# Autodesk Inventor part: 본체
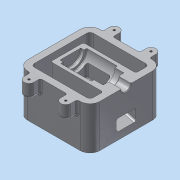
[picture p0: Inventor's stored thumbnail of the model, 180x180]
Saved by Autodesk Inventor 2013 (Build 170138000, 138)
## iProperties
Created: 2018-01
Part Number: 본체
Material: 알루미늄 6061
Document SubType Name: Modeling
Designer: dgall
Density: 2.71 g/cm^3
Mass: 998.337 g
Surface Area: 834.618 cm^2
Volume: 368.39 cm^3
Author: dgall
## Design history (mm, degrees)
sketch "스케치1"
  geometry: L1 (-55, 55)-(55, 55); L2 (55, 55)-(55, -55); L3 (55, -55)-(-55, -55); L4 (-55, -55)-(-55, 55); L5 (45, 45)-(-45, 45); L6 (-45, 45)-(-45, -45); L7 (-45, -45)-(45, -45); L8 (45, -45)-(45, 45); 3 further points
  constraints: 16 end point, 4 parallel, 2 midpoint, 2 perpendicular, 1 horizontal, 1 horizontal alignment, 1 vertical alignment, 3 other
  dimensions: "d0" = 110 distance of L1.start L1.end; "d2" = 110 distance of L1.end L2.end; "d3" = 10 distance between parallel lines of L5 L1
extrude "돌출1" new body sketch "스케치1" distance "d4" = 65; taper "d5" = 0 deg
sketch "스케치2"
  geometry: L1 (55, 55)-(-55, 55) reference; L2 (-55, 55)-(-55, -55) reference; L3 (-35.5, 65)-(-35.5, 55); L4 (-20.5, 65)-(-20.5, 55); L5 (20.5, 65)-(20.5, 55); L6 (35.5, 65)-(35.5, 55); A1 r 7.5 centre (-28, 65) between (-20.5, 65) and (-35.5, 65); A2 r 7.5 centre (28, 65) between (35.5, 65) and (20.5, 65); 1 further point
  constraints: 8 end point, 4 perpendicular, 4 point on circle, 4 point on line, 4 tangent, 2 centre point, 1 equal radius
  dimensions: "d6" = 7.5 radius of A1; "d7" = 10 distance from line of L1 A1.centre; "d8" = 27 distance from line of L2 A1.centre; "d9" = 10 distance from line of L1 A2.centre; "d10" = 56 distance of A2.centre A1.centre
extrude "돌출2" join sketch "스케치2" distance "d11" = 20; taper "d12" = 0 deg
sketch "스케치3"
  geometry: A1 r 7.5 centre (28, 65) between (35.5, 65) and (20.5, 65) reference; A2 r 7.5 centre (-28, 65) between (-20.5, 65) and (-35.5, 65) reference; 3 further points
  constraints: 2 coincident
hole "구멍1" sketch "스케치3" at (-28, 65), (28, 65) diameter "d13" = 3.242; stored, may be unused: countersink angle "d17" = 90 deg, drill point angle "d19" = 118 deg; dims "d14" = 9, "d15" = 4, "d16" = 2, "d18" = 11
fillet "모깎기1" dims "d20" = 15
fillet "모깎기2" dims "d21" = 5
fillet "모깎기3" dims "d22" = 3
sketch "스케치4"
  geometry: L1 (-45, 65)-(-45, 0) reference; L2 (-45, 0)-(-55, 0) reference; L3 (-55, 0)-(-55, 65) reference; L4 (-55, 65)-(-45, 65) reference; L5 (55, 65)-(55, 0) reference; L6 (55, 0)-(45, 0) reference; L7 (45, 0)-(45, 65) reference; L8 (45, 65)-(55, 65) reference; L9 (-45, 8.564)-(35, 30); L10 (40, 0)-(-40, 0) reference; L11 (35, 30)-(35, 65); L12 (35, 65)-(-45, 65); 1 further point
  constraints: 6 end point, 2 perpendicular, 1 point on line
  dimensions: "d23" = 105 deg angle of L9 L1; "d24" = 30 distance from line of L10 L9.end; "d25" = 20 distance between parallel lines of L5 L11
extrude "돌출3" join sketch "스케치4" stored distance "d26" = 50; taper "d27" = 0 deg
sketch "스케치5"
  geometry: L1 (-65, 0)-(-65, 80) reference; C1 r 7.5 at (-65, 40); 1 further point
  constraints: 1 centre point, 1 midpoint
  dimensions: "d28" = 7.5 radius of C1
extrude "돌출4" cut sketch "스케치5" distance "d30" = 85; taper "d31" = 0 deg
sketch "스케치6"
  geometry: C1 r 16 at (-65, 40); A1 r 7.5 centre (-65, 40) between (-65, 32.5) and (-65, 47.5) reference; 1 further point
  constraints: 1 centre point, 1 coincident
  dimensions: "d32" = 16 radius of C1
extrude "돌출5" cut sketch "스케치6" distance "d34" = 66; taper "d35" = 0 deg
node "작업 평면1"
sketch "스케치7"
  geometry: L1 (-27.321, 15)-(-65, 15) reference; L2 (-65, 15)-(-65, 24) reference; L3 (-65, 56)-(-65, 65) reference; L4 (-65, 65)-(-27.321, 65) reference; L5 (-27.321, 65)-(-27.321, 15) reference; L6 (-65, -5)-(0, -5) reference; L7 (0, -5)-(0, -15) reference; L8 (0, -15)-(-42, -15) reference; L9 (-45, -18)-(-45, -28.354) reference; L10 (-48, -31.874)-(-65, -31.874) reference; L11 (-65, -31.874)-(-65, -5) reference; L12 (0, 85)-(-65, 85) reference; L13 (-65, 85)-(-65, 111.874) reference; L14 (-65, 111.874)-(-48, 111.874) reference; L15 (-45, 108.354)-(-45, 98) reference; L16 (-42, 95)-(0, 95) reference; L17 (0, 95)-(0, 85) reference; C1 r 20 at (-65, 40); A1 r 16 centre (-65, 40) between (-65, 24) and (-65, 56) reference; A2 r 3 centre (-42, -18) between (-42, -15) and (-45, -18) reference; A3 r 3 centre (-42, 98) between (-45, 98) and (-42, 95) reference; 1 further point
  constraints: 1 centre point, 1 coincident, 2 other
  dimensions: "d37" = 20 radius of C1
extrude "돌출6" cut sketch "스케치7" distance "d39" = 47; taper "d40" = 0 deg
sketch "스케치8"
  geometry: L1 (35, 65)-(35, 30) reference; L2 (35, 30)-(-45, 8.564) reference; L3 (-45, 8.564)-(-45, 0) reference; L4 (-45, 0)-(-55, 0) reference; L5 (-55, 0)-(-55, 57.5) reference; L6 (-55, 57.5)-(-36, 57.5) reference; L7 (-36, 57.5)-(-36, 49) reference; L8 (-36, 49)-(-22, 49) reference; L9 (-22, 49)-(-22, 45) reference; L10 (-22, 45)-(25, 45) reference; L11 (25, 45)-(25, 49) reference; L12 (25, 49)-(30, 49) reference; L13 (30, 49)-(30, 65) reference; L14 (30, 65)-(35, 65) reference; L15 (55, 65)-(55, 0) reference; L16 (55, 0)-(45, 0) reference; L17 (45, 0)-(45, 65) reference; L18 (45, 65)-(55, 65) reference; L19 (-17, 39.243)-(-55, 29.061); L20 (20, 31.157)-(-55, 11.061); L21 (-17, 39.243)-(-17, 55); L22 (-17, 55)-(20, 55); L23 (20, 55)-(20, 31.157); 1 further point
  constraints: 10 end point, 3 parallel, 2 perpendicular, 2 point on line
  dimensions: "d41" = 5 distance between parallel lines of L2 L20; "d43" = 18 distance of L20.end L19.end; "d45" = 5 distance between parallel lines of L9 L21; "d46" = 37 distance of L21.end L22.end; "d47" = 10 distance between parallel lines of L10 L22
extrude "돌출7" cut sketch "스케치8" stored distance "d48" = 30; taper "d49" = 0 deg
fillet "모깎기4" dims "d50" = 3
fillet "모깎기5" dims "d51" = 3
fillet "모깎기6" dims "d52" = 1
chamfer "모따기1" distance "d53" = 1; stored, may be unused: second distance "d54" = 2, angle "d55" = 45 deg
sketch "스케치9" dims "d11" = 20
  geometry: L1 (0, 0)-(80, 0) reference; L2 (95, -65)-(95, 0) reference; 2 further points
  constraints: 1 other
  dimensions: "d56" = 20 distance from line of L1 point (40, -20); "d57" = 55 distance from line of L2 point (40, -20)
feature "엠보싱1" sketch "스케치9" dims "d0" = 110, "d2" = 110, "d3" = 10, "d58" = 0.5, "d59" = 0
fillet "모깎기7" dims "d60" = 3
fillet "모깎기8" dims "d61" = 3
node "솔리드1"
mirror "대칭1"
node "절단 모서리 투영1"
node "절단 모서리 투영2"
node "절단 모서리 투영3"
other parameters: "d36" = 5
